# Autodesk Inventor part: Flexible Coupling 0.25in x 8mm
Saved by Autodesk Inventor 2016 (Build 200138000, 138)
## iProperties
Created: 2015-11
Part Number: Flexible Coupling 0.25in x 8mm
Material: Generic
Document SubType Name: Modeling
Designer: John
Density: 1 g/cm^3
Appearance: Default
Author: John
Revision Number: ANY
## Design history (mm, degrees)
chamfer "Chamfer1"
body "Solid1"
